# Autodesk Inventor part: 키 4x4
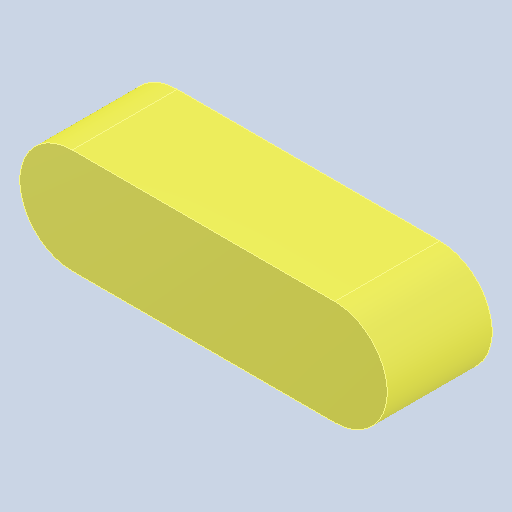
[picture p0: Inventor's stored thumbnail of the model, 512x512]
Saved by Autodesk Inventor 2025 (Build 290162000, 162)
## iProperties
Created: 2024-08
Part Number: 키 4x4
Material: 강철, 연강
Document SubType Name: Modeling
Designer: rese9
Density: 7.86 g/cm^3
Appearance: 기본값
Author: jhkim
Sending System: Autodesk Inventor 2025
Preprocessor: ST-DEVELOPER v20
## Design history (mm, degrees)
feature "솔리드1"
node "솔리드2"
